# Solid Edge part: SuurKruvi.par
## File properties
Author: Egon 815
Template: Normal.par
Last saved by: Egon 815
Revision: 4
Application: Solid Edge
Accuracy: 0,990
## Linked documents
ikeKruvi.par
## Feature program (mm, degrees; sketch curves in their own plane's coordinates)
part copy "CopiedPart_1"  YScale = 10; ZScale = 10
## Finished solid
Body 1: solid body, 13 faces, 36 edges, 30 vertices.
  Faces by surface: plane 5, spline 5, sphere 2, cylinder 1
  Edges by curve: circle 26, intersection 10
Bounding box of the edges (mm; curved faces can reach further): 4297.481 x 1741.241 x 4439.384, from (-2318.5011, -1500, -2259.3193) to (1978.9796, 241.2414, 2180.0643).
Cylindrical faces by radius (mm): R400 x1
Spherical faces by radius (mm): R50 x1, R400 x1
Planar faces by outward normal: -y 1, oblique 4
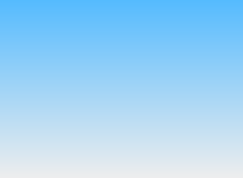
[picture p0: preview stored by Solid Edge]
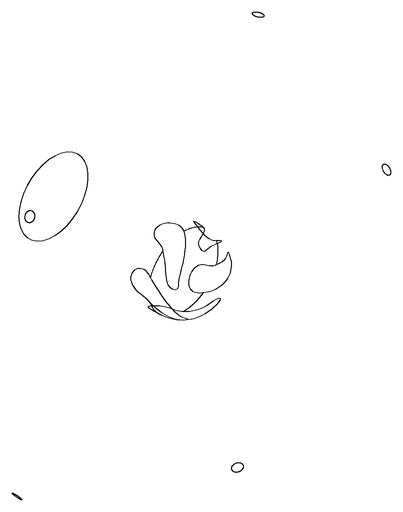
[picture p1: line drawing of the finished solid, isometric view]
